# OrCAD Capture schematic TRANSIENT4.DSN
size A
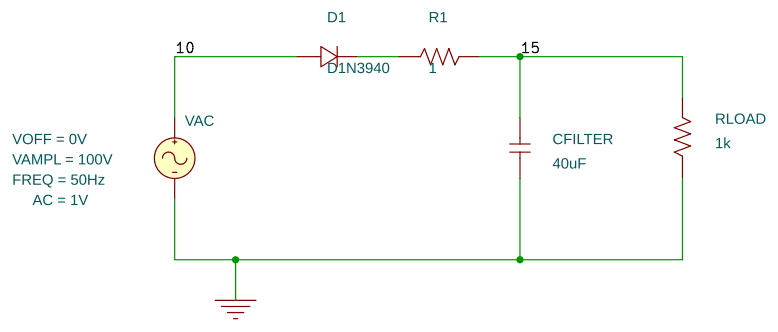
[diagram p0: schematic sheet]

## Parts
CFILTER  40uF  [RAD/CK05]
D1  D1N3940  [DO-13]
R1  1  [AX/RC05]
RLOAD  1k  [AX/RC05]
VAC  VSIN

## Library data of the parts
CFILTER = C
D1 = D1N3940
R1 RLOAD = R
VAC = VSIN: AC: 1V; FREQ: 50Hz; VAMPL: 100V; VOFF: 0V

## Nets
0: CFILTER.1 RLOAD.1 VAC.2(-)
10: D1.1 VAC.1(+)
15: CFILTER.2 R1.2 RLOAD.2
N00848: D1.2 R1.1
